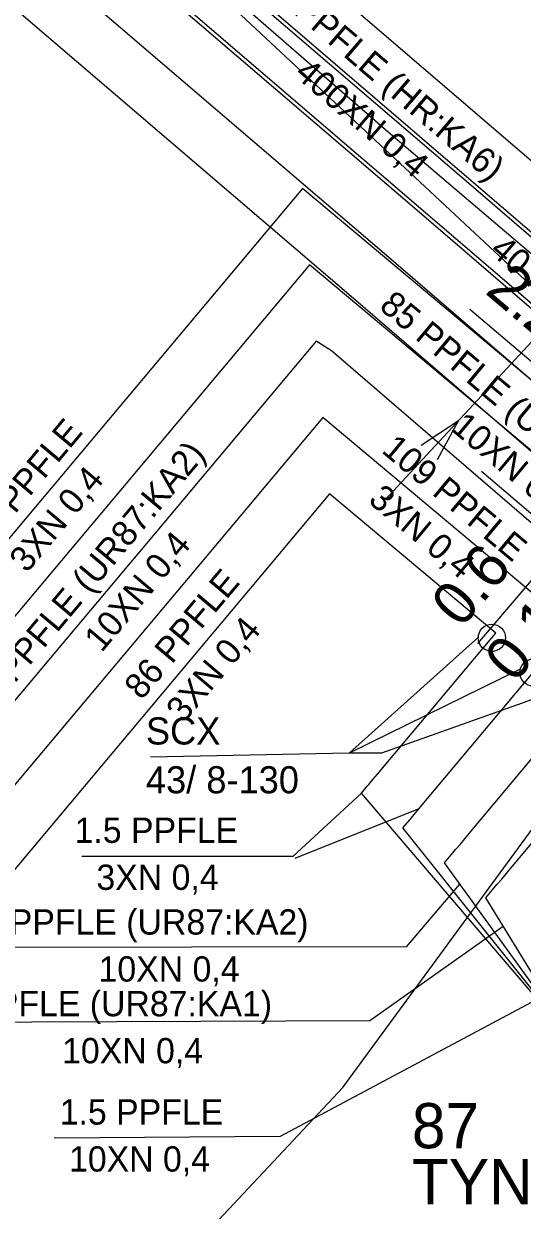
# Model space of a CAD drawing. Extents: x -756413 to -755757, y -1139003 to -1138237.
# Drawn here: x -756295.44 to -756288.54, y -1138383.61 to -1138367.2 of the extents above; entities that cross this region are included whole.
import ezdxf

# ---------------------------------------------------------------- set-up
doc = ezdxf.new("R2010")
doc.units = 0
for name, color, linetype in [('f006_osa_trasy', 7, 'Continuous'), ('f006_stp_koty', 7, 'Continuous'), ('f006_stp_linie', 7, 'Continuous'), ('f307_kabel_metal', 7, 'Continuous'), ('f307_kabel_metal_ann', 7, 'Continuous'), ('f307_rozvadec_ann', 7, 'Continuous'), ('f307_spojka_metal', 7, 'Continuous'), ('f307_spojka_metal_ann', 7, 'Continuous'), ('f309_trubka', 7, 'Continuous'), ('f373_cerch_cara', 7, 'Continuous')]:
    doc.layers.add(name, color=color, linetype=linetype)

msp = doc.modelspace()

# ---------------------------------------------------------------- linework, layer by layer
at = {"layer": 'f006_osa_trasy'}
for points in [[(-756282.83, -1138375.12), (-756286.84, -1138371.72), (-756290.36, -1138368.73), (-756302.28, -1138358.38), (-756303.67, -1138357.72), (-756311.7, -1138350.6)], [(-756290.62, -1138387.46), (-756284.79, -1138379.7), (-756282.11, -1138376.17), (-756288.02, -1138371.19), (-756301.12, -1138358.98), (-756302.2, -1138358.1), (-756303.05, -1138358.15), (-756304.87, -1138359.66)], [(-756312.22, -1138404.34), (-756311.43, -1138403.06), (-756307.8, -1138399.78), (-756302.65, -1138394.53), (-756298.44, -1138390.08), (-756293.77, -1138384.84), (-756291.02, -1138381.91), (-756287.55, -1138377.18), (-756286, -1138374.68), (-756285.31, -1138374.59), (-756283.34, -1138375.8)]]:
    msp.add_lwpolyline(points, dxfattribs=at)
at = {"layer": 'f006_stp_koty'}
for p, q in [((-756290.438, -1138373.79), (-756286.053, -1138369.053)), ((-756289.262, -1138371.148), (-756284.127, -1138375.514)), ((-756285.948, -1138371.997), (-756289.156, -1138375.771)), ((-756284.479, -1138377.324), (-756289.103, -1138373.393))]:
    msp.add_line(p, q, dxfattribs=at)
msp.add_lwpolyline([(-756289.937, -1138373.028), (-756289.42, -1138372.69), (-756289.717, -1138373.232)], dxfattribs=at)
at = {"layer": 'f006_stp_linie'}
msp.add_lwpolyline([(-756325.53, -1138418.96), (-756324.32, -1138416.51), (-756322.61, -1138413.84), (-756321.49, -1138412.22), (-756320.41, -1138411.21), (-756318.19, -1138409.32), (-756315.85, -1138407.31), (-756315.25, -1138406.9), (-756313.95, -1138405.81), (-756312.72, -1138405.17), (-756312.44, -1138404.71), (-756312.22, -1138404.34), (-756311.43, -1138403.06), (-756307.8, -1138399.78), (-756302.65, -1138394.53), (-756298.44, -1138390.08), (-756293.77, -1138384.84), (-756291.02, -1138381.91), (-756287.55, -1138377.18), (-756286, -1138374.68), (-756285.31, -1138374.59), (-756283.34, -1138375.8), (-756282.74, -1138376.16)], dxfattribs=at)
at = {"layer": 'f307_kabel_metal'}
msp.add_line((-756312.023, -1138350.844), (-756283.054, -1138375.657), dxfattribs=at)
for points in [[(-756310.454, -1138350.213), (-756282.069, -1138374.526), (-756282.051, -1138374.542), (-756279.377, -1138376.935), (-756278.838, -1138377.392), (-756272.1, -1138382.766), (-756271.532, -1138383.148), (-756268.323, -1138385.294), (-756262.071, -1138388.934), (-756261.451, -1138389.235), (-756257.195, -1138391.284), (-756251.577, -1138393.575), (-756242.922, -1138395.724), (-756234.355, -1138397.059), (-756233.614, -1138397.174), (-756219.271, -1138399.407)], [(-756310.942, -1138350.783), (-756282.566, -1138375.087), (-756282.554, -1138375.098), (-756279.87, -1138377.5), (-756279.315, -1138377.971), (-756272.544, -1138383.371), (-756271.95, -1138383.771), (-756268.72, -1138385.93), (-756262.424, -1138389.596), (-756261.778, -1138389.91), (-756257.5, -1138391.97), (-756251.81, -1138394.29), (-756243.07, -1138396.46), (-756234.47, -1138397.8), (-756233.729, -1138397.915), (-756219.383, -1138400.149)], [(-756284.683, -1138375.264), (-756284.676, -1138375.255), (-756291.577, -1138369.478), (-756295.006, -1138373.564), (-756295.13, -1138373.711), (-756298.544, -1138377.773), (-756318.688, -1138398.187), (-756319.519, -1138397.43)], [(-756285.765, -1138375.387), (-756285.733, -1138375.348), (-756291.484, -1138370.534), (-756294.432, -1138374.047), (-756294.556, -1138374.194), (-756297.989, -1138378.278), (-756318.66, -1138399.227), (-756319.205, -1138399.742), (-756330.074, -1138410.117), (-756326.605, -1138419.746), (-756341.343, -1138432.472)], [(-756286.972, -1138375.658), (-756286.816, -1138375.476), (-756291.179, -1138371.724), (-756291.391, -1138371.59), (-756293.858, -1138374.53), (-756293.982, -1138374.677), (-756297.434, -1138378.783), (-756318.135, -1138399.763), (-756318.689, -1138400.286), (-756329.203, -1138410.322), (-756325.725, -1138419.977), (-756325.47, -1138420.682), (-756325.148, -1138421.576), (-756313.125, -1138448.388), (-756305.964, -1138469.586), (-756306.39, -1138472.389), (-756307.168, -1138474.638), (-756308.162, -1138475.59), (-756309.285, -1138475.849), (-756315.462, -1138479.353)], [(-756288.384, -1138376.174), (-756287.902, -1138375.6), (-756287.847, -1138375.534), (-756291.298, -1138372.646), (-756293.284, -1138375.013), (-756293.408, -1138375.16), (-756296.879, -1138379.289), (-756317.519, -1138400.206), (-756328.332, -1138410.527), (-756324.452, -1138421.295), (-756312.811, -1138447.256), (-756304.831, -1138441.703), (-756301.921, -1138444.882), (-756300.466, -1138443.292)], [(-756288.958, -1138375.692), (-756288.904, -1138375.627), (-756291.205, -1138373.702), (-756292.71, -1138375.496), (-756292.834, -1138375.643), (-756296.324, -1138379.794), (-756316.993, -1138400.741), (-756327.461, -1138410.732), (-756323.756, -1138421.014), (-756320.657, -1138427.925), (-756318.754, -1138427.003), (-756311.742, -1138419.982)], [(-756287.798, -1138381.308), (-756289.039, -1138379.287), (-756288.887, -1138379.105), (-756288.822, -1138379.029), (-756288.697, -1138378.88), (-756285.765, -1138375.387)], [(-756287.798, -1138381.308), (-756290.762, -1138377.84), (-756290.683, -1138377.744), (-756290.663, -1138377.72), (-756290.644, -1138377.699), (-756290.607, -1138377.654), (-756290.541, -1138377.576), (-756290.421, -1138377.434), (-756288.958, -1138375.692)], [(-756287.798, -1138381.308), (-756289.613, -1138378.805), (-756289.496, -1138378.664), (-756289.46, -1138378.621), (-756289.394, -1138378.544), (-756289.272, -1138378.398), (-756286.972, -1138375.658)], [(-756287.798, -1138381.308), (-756290.188, -1138378.322), (-756290.091, -1138378.206), (-756290.072, -1138378.184), (-756290.032, -1138378.136), (-756289.967, -1138378.059), (-756289.847, -1138377.916), (-756288.384, -1138376.174)]]:
    msp.add_lwpolyline(points, dxfattribs=at)
at = {"layer": 'f307_spojka_metal'}
for centre in [(-756288.958, -1138375.692), (-756288.384, -1138376.174)]:
    msp.add_circle(centre, 0.188, dxfattribs=at)
at = {"layer": 'f309_trubka'}
for points in [[(-756310.552, -1138351.565), (-756303.608, -1138357.783), (-756301.98, -1138358.543), (-756289.41, -1138369.29), (-756273.581, -1138382.899), (-756267.391, -1138386.699), (-756260.769, -1138390.604), (-756251.313, -1138394.329), (-756242.348, -1138396.659), (-756226.133, -1138399.092), (-756211.588, -1138401.296), (-756190.711, -1138405.458), (-756180.192, -1138409.372), (-756170.888, -1138414.389), (-756161.932, -1138421.301), (-756154.261, -1138427.534)], [(-756311.061, -1138352.116), (-756304.026, -1138358.416), (-756302.39, -1138359.179), (-756289.898, -1138369.859), (-756274.024, -1138383.507), (-756267.778, -1138387.342), (-756261.099, -1138391.28), (-756251.546, -1138395.043), (-756242.498, -1138397.395), (-756226.245, -1138399.834), (-756211.718, -1138402.035), (-756190.916, -1138406.182), (-756180.502, -1138410.057), (-756171.298, -1138415.02), (-756162.398, -1138421.889), (-756154.878, -1138427.999)], [(-756311.57, -1138352.667), (-756304.444, -1138359.049), (-756302.8, -1138359.815), (-756290.386, -1138370.428), (-756274.468, -1138384.115), (-756268.165, -1138387.985), (-756261.429, -1138391.956), (-756251.779, -1138395.757), (-756242.648, -1138398.131), (-756226.357, -1138400.576), (-756211.848, -1138402.774), (-756191.121, -1138406.906), (-756180.812, -1138410.742), (-756171.708, -1138415.651), (-756162.864, -1138422.477), (-756155.495, -1138428.464)], [(-756312.079, -1138353.218), (-756304.862, -1138359.682), (-756303.21, -1138360.452), (-756290.874, -1138370.997), (-756274.912, -1138384.723), (-756268.552, -1138388.628), (-756261.759, -1138392.632), (-756252.012, -1138396.471), (-756242.798, -1138398.867), (-756226.469, -1138401.318), (-756211.978, -1138403.513), (-756191.326, -1138407.63), (-756181.122, -1138411.427), (-756172.118, -1138416.282), (-756163.33, -1138423.065), (-756156.112, -1138428.929), (-756154.994, -1138431.554)]]:
    msp.add_lwpolyline(points, dxfattribs=at)
at = {"layer": 'f373_cerch_cara'}
for p, q in [((-756288.558, -1138376.121), (-756290.935, -1138377.287)), ((-756289.967, -1138378.059), (-756291.684, -1138378.745))]:
    msp.add_line(p, q, dxfattribs=at)
for points in [[(-756284.867, -1138375.29), (-756290.484, -1138377.288), (-756290.935, -1138377.287)], [(-756289.138, -1138375.677), (-756290.935, -1138377.287), (-756293.685, -1138377.343)], [(-756290.762, -1138377.84), (-756291.715, -1138378.715), (-756294.634, -1138378.715)], [(-756289.406, -1138379.098), (-756290.146, -1138379.966), (-756296.091, -1138379.974)], [(-756288.801, -1138379.683), (-756290.648, -1138380.99), (-756296.497, -1138381.011)], [(-756287.861, -1138380.439), (-756291.887, -1138382.589), (-756295.017, -1138382.609)]]:
    msp.add_lwpolyline(points, dxfattribs=at)

# ---------------------------------------------------------------- texts
at = {"layer": 'f006_stp_koty'}
for s, rotation, p in [('2.2', 319.63, (-756289.067, -1138370.919)), ('0.6', 49.63, (-756289.384, -1138375.575)), ('0.1', 49.63, (-756288.645, -1138376.334))]:
    msp.add_text(s, height=0.6, rotation=rotation, dxfattribs=at).set_placement(p)
at = {"layer": 'f307_kabel_metal_ann'}
for s, rotation, p in [('475 PPFLE (HR:KA6)', 319.42, (-756292.414, -1138366.455)), (' 400XN 0,4', 319.42, (-756291.805, -1138367.832)), ('40 PPFLE (HR:KA5)', 319.42, (-756289.003, -1138370.364)), ('85 PPFLE (UR87:KA1)', 320.07, (-756290.533, -1138371.135)), (' 10XN 0,4', 320.07, (-756289.642, -1138372.728)), ('45 PPFLE', 50, (-756295.977, -1138374.488)), ('109 PPFLE', 320.08, (-756290.499, -1138373.12)), ('159 PPFLE (UR87:KA2)', 50, (-756296.15, -1138377.028)), (' 3XN 0,4', 50, (-756295.48, -1138374.907)), (' 3XN 0,4', 320.08, (-756290.784, -1138373.729)), (' 10XN 0,4', 50, (-756294.444, -1138376.006)), ('86 PPFLE', 49.85, (-756293.808, -1138376.565)), (' 3XN 0,4', 49.85, (-756293.312, -1138376.985))]:
    msp.add_text(s, height=0.35, rotation=rotation, dxfattribs=at).set_placement(p)
for s, p in [('1.5 PPFLE', (-756294.734, -1138378.528)), (' 3XN 0,4', (-756294.562, -1138379.178)), ('1.5 PPFLE (UR87:KA2)', (-756296.412, -1138379.796)), (' 10XN 0,4', (-756294.532, -1138380.446)), ('1.5 PPFLE (UR87:KA1)', (-756296.917, -1138380.926)), (' 10XN 0,4', (-756295.037, -1138381.576)), ('1.5 PPFLE', (-756294.94, -1138382.423)), (' 10XN 0,4', (-756294.941, -1138383.073))]:
    msp.add_text(s, height=0.35, dxfattribs=at).set_placement(p)
at = {"layer": 'f307_rozvadec_ann'}
for s, p in [('87', (-756290.065, -1138382.751)), ('TYNV257', (-756290.064, -1138383.526))]:
    msp.add_text(s, height=0.625, dxfattribs=at).set_placement(p)
at = {"layer": 'f307_spojka_metal_ann'}
for s, p in [('SCX', (-756293.747, -1138377.168)), ('43/ 8-130', (-756293.747, -1138377.843))]:
    msp.add_text(s, height=0.375, dxfattribs=at).set_placement(p)

doc.saveas('drawing.dxf')
